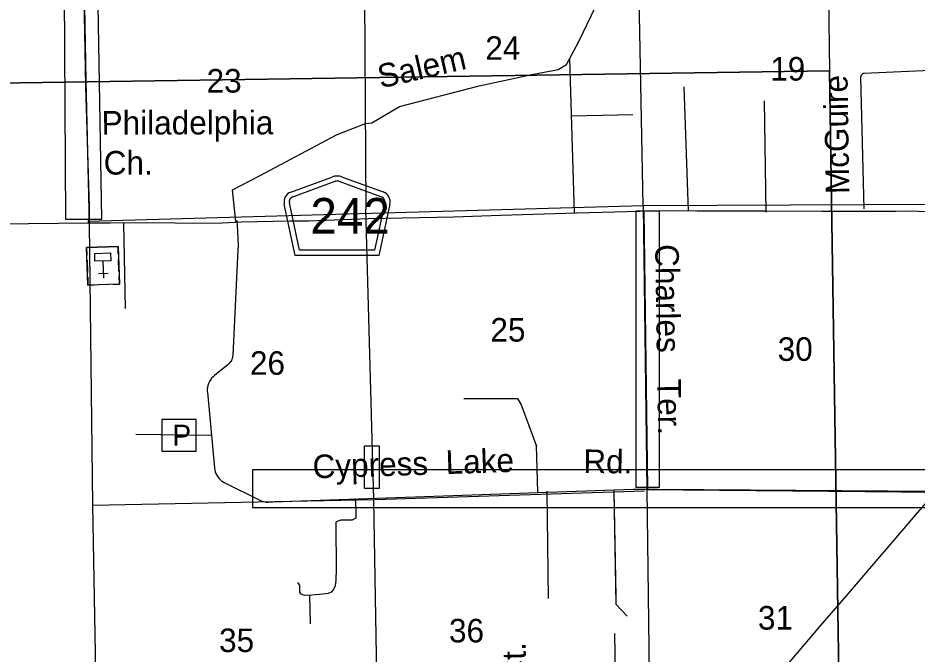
# Model space of a CAD drawing. Extents: x 2480962 to 2688785, y 277103 to 599240.
# Drawn here: x 2506277 to 2523441, y 402321 to 414470 of the extents above; entities that cross this region are included whole.
import ezdxf

# ---------------------------------------------------------------- set-up
doc = ezdxf.new("R2010")
doc.units = 0
for name, color, linetype in [('County Boundary', 7, 'Continuous'), ('County Routes Highway Center Lines', 7, 'Continuous'), ('Culture', 7, 'Continuous'), ('Culture Text', 7, 'Continuous'), ('Divided_Highway', 7, 'Continuous'), ('Level 31', 7, 'Continuous'), ('Local Roads Improved', 7, 'Continuous'), ('Local Roads Paved', 7, 'Continuous'), ('Local Roads Related Cells', 7, 'Continuous'), ('Local Roads Related Text', 7, 'Continuous'), ('Local Roads Unimproved', 7, 'Continuous'), ('Roadshields County Roads', 7, 'Continuous'), ('Section Lines', 7, 'Continuous'), ('Section Numbers', 7, 'Continuous'), ('State Routes Highway Center Lines', 7, 'Continuous'), ('Township and Range lines', 7, 'Continuous')]:
    doc.layers.add(name, color=color, linetype=linetype)

msp = doc.modelspace()

# ---------------------------------------------------------------- linework, layer by layer
at = {"layer": 'County Boundary'}
for points in [[(2507243.503, 438826.865), (2507259.011, 436986.338), (2507326.98, 431727.302), (2507393.895, 426406.177), (2507435.759, 421022.612), (2507527.48, 415779.942), (2507569.561, 413275.686)], [(2507569.561, 413275.686), (2507636.143, 410528.937), (2507701.382, 405162.475), (2507794.025, 399870.396), (2507974.751, 394561.505)]]:
    msp.add_lwpolyline(points, dxfattribs=at)
at = {"layer": 'County Routes Highway Center Lines'}
msp.add_lwpolyline([(2523895.463, 410760.964), (2523260.98, 410778.347), (2523030.654, 410774.002), (2521626.969, 410774.002), (2520566.6, 410778.347), (2519693.1, 410778.347), (2519245.485, 410778.347), (2518789.179, 410787.039), (2518219.882, 410782.693), (2518146.004, 410774.002), (2516946.571, 410743.581), (2515486.391, 410700.123), (2514599.853, 410665.357), (2512961.496, 410634.937), (2511831.595, 410591.479), (2511462.204, 410587.133), (2510540.9, 410569.75), (2510175.855, 410552.367), (2509636.979, 410543.675), (2509271.934, 410552.367), (2508724.366, 410556.713), (2508037.734, 410552.367), (2507607.502, 410548.021), (2504778.403, 410517.601)], dxfattribs=at)
at = {"layer": 'Culture'}
for p, q in [((2508186.925, 410107.982), (2507587.308, 410086.553)), ((2507587.308, 410086.553), (2507592.665, 409936.649)), ((2508192.282, 409958.077), (2508186.925, 410107.982)), ((2507595.879, 409846.706), (2507604.451, 409606.859)), ((2507896.759, 409827.44), (2507908.529, 409498.107)), ((2508204.068, 409628.288), (2508195.496, 409868.135)), ((2507995.273, 409590.807), (2507815.388, 409584.378)), ((2507607.665, 409516.917), (2507613.022, 409367.013)), ((2508002.773, 409380.942), (2507822.888, 409374.513)), ((2508092.716, 409384.156), (2508212.639, 409388.442)), ((2508212.639, 409388.442), (2508207.282, 409538.345)), ((2507613.022, 409367.013), (2507732.945, 409371.299))]:
    msp.add_line(p, q, dxfattribs=at)
for points in [[(2508212.639, 409388.442), (2507613.022, 409367.013), (2507587.308, 410086.553), (2508186.925, 410107.982)], [(2508046.663, 409832.797), (2507746.855, 409822.083), (2507741.498, 409971.987), (2508041.306, 409982.701)]]:
    msp.add_lwpolyline(points, close=True, dxfattribs=at)
at = {"layer": 'Divided_Highway'}
for p, q in [((2521075.087, 458914.627), (2521773.243, 413460.785)), ((2482259.128, 412874.994), (2521773.243, 413460.785)), ((2521773.243, 413460.785), (2482259.128, 412874.994)), ((2482259.128, 412874.994), (2521773.243, 413460.785)), ((2521773.243, 413460.785), (2482259.128, 412874.994)), ((2482259.128, 412874.994), (2521773.243, 413460.785)), ((2521773.243, 413460.785), (2482259.128, 412874.994)), ((2522471.387, 368007.737), (2521773.243, 413460.785)), ((2521773.243, 413460.785), (2522471.387, 368007.737)), ((2521773.243, 413460.785), (2522471.387, 368007.737)), ((2521773.243, 413460.785), (2522471.387, 368007.737)), ((2522471.387, 368007.737), (2521773.243, 413460.785)), ((2522471.387, 368007.737), (2521773.243, 413460.785)), ((2521773.243, 413460.785), (2522471.387, 368007.737)), ((2521773.243, 413460.785), (2522471.387, 368007.737)), ((2521773.243, 413460.785), (2522471.387, 368007.737)), ((2521773.243, 413460.785), (2522471.387, 368007.737)), ((2521773.243, 413460.785), (2522471.387, 368007.737))]:
    msp.add_line(p, q, dxfattribs=at)
at = {"layer": 'Level 31'}
for points in [[(2507181.708, 410624.195), (2507875.09, 410624.668), (2507671.446, 422513.909), (2507113.793, 422529.957)], [(2518080.878, 410787.075), (2518515.847, 410787.075), (2518515.847, 405503.787), (2518080.878, 405503.787)], [(2512891.515, 406299.767), (2513170.505, 406299.767), (2513170.505, 405483.71), (2512891.515, 405483.71)], [(2510751.352, 405117.676), (2523857.098, 405117.676), (2523857.098, 405837.626), (2510751.352, 405837.626)]]:
    msp.add_lwpolyline(points, close=True, dxfattribs=at)
at = {"layer": 'Local Roads Improved'}
for p, q in [((2516904.761, 410743.311), (2516812.772, 413681.862)), ((2522365.158, 413338.157), (2522425.529, 410826.7)), ((2524299.075, 413493.425), (2522433.007, 413410.805)), ((2518225.409, 410780.349), (2518293.951, 405483.31)), ((2510453.651, 410601.612), (2510470.589, 410396.903)), ((2508289.183, 410550.364), (2508320.209, 408918.356)), ((2510476.501, 410038.849), (2510376.781, 408027.26)), ((2510287.054, 407851.33), (2510028.876, 407643.795)), ((2509892.668, 407321.461), (2510029.038, 405876.532)), ((2509958.198, 406495.439), (2508528.636, 406512.357)), ((2516167.186, 406306.038), (2516193.984, 405414.168)), ((2510223.428, 405592.611), (2510878.513, 405264.642)), ((2511140.54, 405226.011), (2518024.698, 405471.373)), ((2518024.698, 405471.373), (2518501.097, 405470.183)), ((2518501.097, 405470.183), (2523762.386, 405432.509))]:
    msp.add_line(p, q, dxfattribs=at)
for points in [[(2510432.847, 410582.63), (2510371.22, 411186.573), (2510888.886, 411457.732), (2512367.932, 412246.556), (2512910.249, 412456.088), (2513033.502, 412468.413), (2513563.494, 412776.547), (2515079.515, 413170.96), (2516090.196, 413392.816), (2516586.78, 413485.395), (2516747.01, 413583.998), (2516989.949, 414033.736), (2517294.439, 414670.748), (2517427.312, 414755.071), (2517961.362, 414757.627), (2518025.243, 414753.794)], [(2522433.007, 413410.805), (2522425.609, 413410.088), (2522418.326, 413408.601), (2522411.239, 413406.362), (2522404.424, 413403.394), (2522397.957, 413399.731), (2522391.909, 413395.41), (2522386.346, 413390.482), (2522381.328, 413384.999), (2522376.91, 413379.021), (2522373.142, 413372.614), (2522370.063, 413365.849), (2522367.709, 413358.799), (2522366.105, 413351.541), (2522365.268, 413344.156), (2522365.158, 413338.157)], [(2510470.589, 410396.903), (2510479.163, 410113.054), (2510476.501, 410038.849)], [(2510376.781, 408027.26), (2510374.215, 408002.162), (2510369.039, 407977.469), (2510361.31, 407953.452), (2510351.115, 407930.376), (2510338.562, 407908.491), (2510323.791, 407888.038), (2510306.962, 407869.241), (2510288.261, 407852.307), (2510287.054, 407851.33)], [(2510028.876, 407643.795), (2510000.075, 407618.049), (2509974.123, 407589.435), (2509951.303, 407558.264), (2509931.868, 407524.879), (2509916.028, 407489.645), (2509903.958, 407452.949), (2509895.79, 407415.191), (2509891.613, 407376.787), (2509891.473, 407338.156), (2509892.668, 407321.461)], [(2510029.038, 405876.532), (2510034.458, 405839.792), (2510043.688, 405803.819), (2510056.628, 405769.009), (2510073.136, 405735.741), (2510093.03, 405704.382), (2510116.094, 405675.275), (2510142.073, 405648.737), (2510170.685, 405625.062), (2510201.614, 405604.506), (2510223.428, 405592.611)], [(2510878.513, 405264.642), (2510920.355, 405246.367), (2510963.878, 405232.565), (2511008.605, 405223.389), (2511054.047, 405218.938), (2511140.54, 405226.011)], [(2512711.96, 405293.814), (2512726.907, 405044.693), (2512726.907, 404950.028), (2512726.907, 404915.151), (2512657.153, 404875.291), (2512597.364, 404875.291), (2512437.927, 404875.291), (2512383.12, 404860.344), (2512348.243, 404840.414), (2512343.261, 404785.608), (2512353.226, 403943.58), (2512348.243, 403729.336), (2512333.296, 403624.705), (2512303.402, 403554.951), (2512253.578, 403505.127), (2512198.771, 403480.215), (2512094.14, 403465.268), (2511884.879, 403445.338), (2511745.371, 403440.356), (2511680.6, 403465.268), (2511655.688, 403505.127), (2511655.688, 403564.916), (2511655.688, 403594.81), (2511655.688, 403629.687), (2511640.74, 403659.582), (2511620.811, 403684.494)]]:
    msp.add_lwpolyline(points, dxfattribs=at)
at = {"layer": 'Local Roads Paved'}
for p, q in [((2507430.11, 421188.106), (2507563.419, 413169.209)), ((2507563.419, 413169.209), (2507638.176, 410858.319))]:
    msp.add_line(p, q, dxfattribs=at)
msp.add_lwpolyline([(2507638.176, 410858.319), (2507634.911, 410695.312), (2507617.637, 410550.922)], dxfattribs=at)
at = {"layer": 'Local Roads Related Cells'}
for p, q in [((2509025.941, 406800.624), (2509025.941, 406197.421)), ((2509679.143, 406800.624), (2509025.941, 406800.624)), ((2509679.143, 406197.421), (2509679.143, 406800.624)), ((2509025.941, 406197.421), (2509679.143, 406197.421))]:
    msp.add_line(p, q, dxfattribs=at)
at = {"layer": 'Local Roads Unimproved'}
for p, q in [((2519076.734, 410779.084), (2518994.965, 413155.478)), ((2520558.785, 410758.642), (2520528.122, 412884.62)), ((2516843.435, 412603.541), (2518013.745, 412623.983)), ((2517653.723, 405439.479), (2517688.949, 403417.506)), ((2516376.133, 405429.727), (2516401.382, 403379.927)), ((2511845.019, 403440.356), (2511854.984, 402897.272)), ((2517718.415, 400196.808), (2517672.496, 402710.033))]:
    msp.add_line(p, q, dxfattribs=at)
for points in [[(2514786.327, 407200.779), (2515765.61, 407200.779), (2515814.926, 407200.779), (2515885.378, 407081.01), (2516174.231, 406291.948)], [(2517654.516, 405412.42), (2517688.628, 403271.531), (2517904.815, 403043.751)]]:
    msp.add_lwpolyline(points, dxfattribs=at)
at = {"layer": 'Roadshields County Roads'}
for p, q in [((2511486.689, 411145.411), (2512266.063, 411431.748)), ((2511521.174, 411051.545), (2512335.034, 411350.552)), ((2512404.005, 411350.552), (2513216.513, 411052.041)), ((2512472.976, 411431.748), (2513250.998, 411145.908)), ((2511651.494, 410033.585), (2511457.881, 410936.718)), ((2513279.806, 410937.214), (2513086.086, 410033.585)), ((2511570.66, 409933.585), (2511360.103, 410915.756)), ((2513377.584, 410916.254), (2513166.92, 409933.585)), ((2513166.92, 409933.585), (2511570.66, 409933.585)), ((2513086.086, 410033.585), (2511651.494, 410033.585))]:
    msp.add_line(p, q, dxfattribs=at)
for centre, radius, start, end in [((2512369.52, 411150.151), 300, 69.8269806, 110.1730139), ((2512369.52, 411256.686), 100, 69.8269876, 110.1729839), ((2511555.66, 410957.68), 200, 110.1729839, 192.0998896), ((2513182.028, 410958.176), 200, 347.9000917, 69.8270083), ((2511555.66, 410957.68), 100, 110.1729839, 192.0998896), ((2513182.028, 410958.176), 100, 347.9000932, 69.8269876)]:
    msp.add_arc(centre, radius, start, end, dxfattribs=at)
at = {"layer": 'Section Lines'}
for p, q in [((2512885.38, 415919.881), (2512917.551, 410819.762)), ((2518214.002, 410880.178), (2507610.328, 410581.959)), ((2513069.941, 405271.952), (2512917.551, 410819.762)), ((2523901.822, 410909.308), (2518214.002, 410880.178)), ((2518280.668, 405463.434), (2524081.614, 405409.387)), ((2507695.594, 405162.357), (2513069.941, 405271.952)), ((2513062.973, 405262.964), (2513249.986, 394731.482)), ((2518239.754, 405430.898), (2513088.534, 405263.875))]:
    msp.add_line(p, q, dxfattribs=at)
at = {"layer": 'State Routes Highway Center Lines'}
msp.add_lwpolyline([(2523787.803, 405410.26), (2523408.946, 404974.154), (2522961.054, 404450.491), (2522612.506, 404044.693), (2522242.069, 403611.955), (2522085.475, 403430.104), (2521588.752, 402852.559), (2521193.057, 402389.512), (2520905.127, 402052.751)], dxfattribs=at)
at = {"layer": 'Township and Range lines'}
for p, q in [((2518214.002, 410880.178), (2518115.187, 416063.971)), ((2518214.002, 410880.178), (2518280.668, 405463.434)), ((2518280.668, 405463.434), (2518349.051, 400322.779))]:
    msp.add_line(p, q, dxfattribs=at)

# ---------------------------------------------------------------- texts
at = {"layer": 'Culture Text'}
for s, rotation, p in [('Philadelphia', 0.0668833, (2507872.918, 412243.197)), ('Ch.', 0.0668889, (2507912.553, 411478.456))]:
    msp.add_text(s, height=450, rotation=rotation, dxfattribs=at).set_placement(p)
at = {"layer": 'Local Roads Related Text'}
for s, rotation, p in [('Salem', 12.8365639, (2513201.301, 413123.168)), ('McGuire', 90.9346417, (2522150.322, 411110.08)), ('Charles   Ter.', 270.9346278, (2518440.349, 410146.257)), ('Cypress  Lake', 1.8816722, (2511908.164, 405674.258)), ('Rd.', 359.4663028, (2517068.748, 405779.038)), ('Noel Ct.', 91.4881222, (2516021.17, 400377.136))]:
    msp.add_text(s, height=450, rotation=rotation, dxfattribs=at).set_placement(p)
msp.add_text('P', height=400, dxfattribs=at).set_placement((2509225.348, 406300.678))
at = {"layer": 'Roadshields County Roads'}
msp.add_text('242', height=680, dxfattribs=at).set_placement((2511859.528, 410351.868))
at = {"layer": 'Section Numbers'}
for s, rotation, p in [('24', 0.0292389, (2515199.054, 413670.281)), ('19', 0.0292417, (2520639.312, 413273.693)), ('23', 0.0292417, (2509877.89, 413044.58)), ('25', 0.0292722, (2515296.543, 408288.009)), ('30', 0.029275, (2520781, 407920.565)), ('26', 0.029275, (2510705.136, 407653.722)), ('31', 0.0293083, (2520404.386, 402787.252)), ('36', 0.0293083, (2514505.412, 402543.06)), ('35', 0.0293083, (2510115.999, 402358.371))]:
    msp.add_text(s, height=450, rotation=rotation, dxfattribs=at).set_placement(p)

doc.saveas('drawing.dxf')
